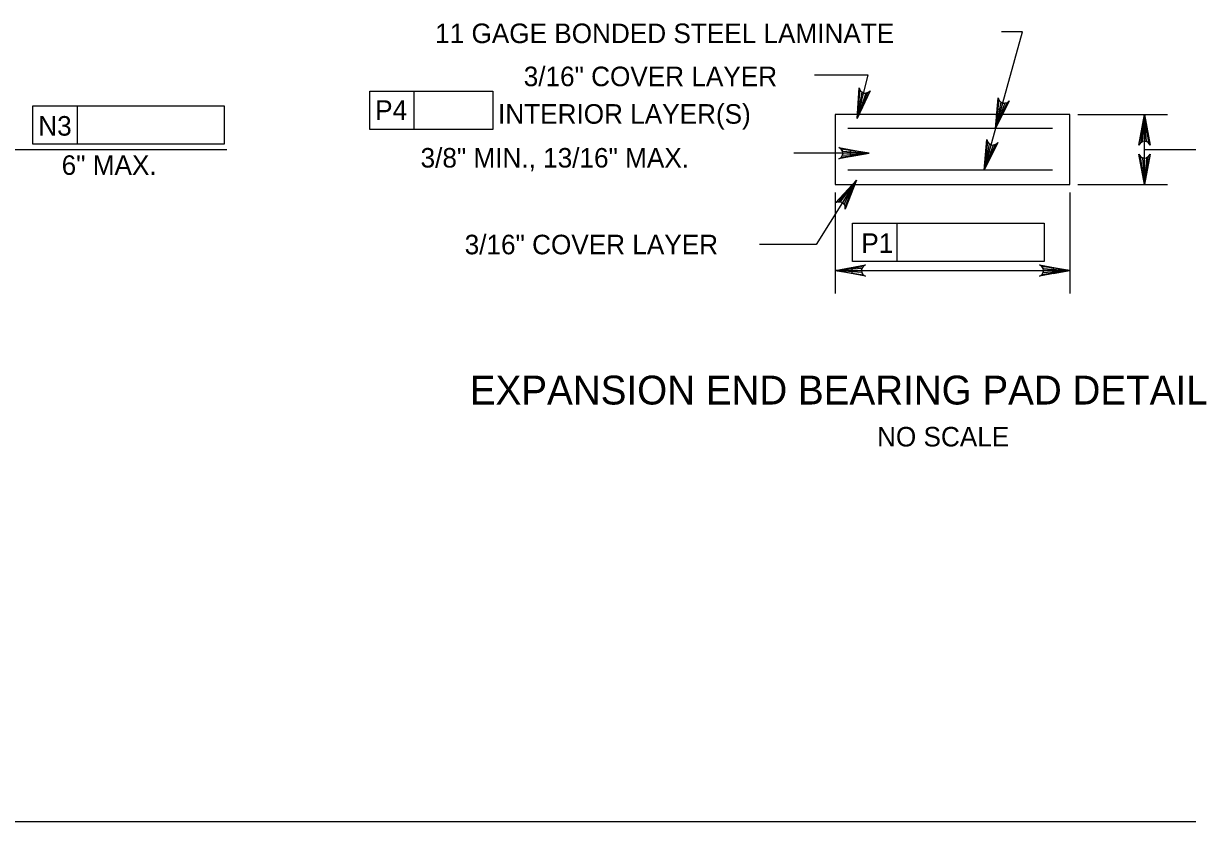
# Model space of a CAD drawing. Extents: x 638175 to 640495, y 294277 to 298435.
# Drawn here: x 639473 to 639651.7, y 297262.5 to 297385 of the extents above; entities that cross this region are included whole.
import ezdxf

# ---------------------------------------------------------------- set-up
doc = ezdxf.new("R2010")
doc.units = 0
for name, color, linetype in [('2', 7, 'Continuous'), ('3', 7, 'Continuous'), ('4', 7, 'Continuous'), ('5', 7, 'Continuous'), ('6', 7, 'Continuous'), ('7', 7, 'Continuous')]:
    doc.layers.add(name, color=color, linetype=linetype)

msp = doc.modelspace()

# ---------------------------------------------------------------- linework, layer by layer
at = {"layer": '2'}
for p, q in [((639597.54, 297359), (639597.54, 297343.49)), ((639633.57, 297359), (639633.57, 297343.49)), ((639597.54, 297347.03), (639633.57, 297347.03)), ((640102.46, 297262.46), (639316.46, 297262.46))]:
    msp.add_line(p, q, dxfattribs=at)
for points in [[(639600.91, 297370.35), (639601.22, 297375.08), (639601.38, 297374.67), (639601.63, 297374.41), (639601.92, 297374.28), (639602.24, 297374.26), (639602.59, 297374.36), (639602.92, 297374.64), (639600.91, 297370.35), (639602.59, 297374.36), (639602.24, 297374.26), (639600.91, 297370.35), (639601.92, 297374.28), (639601.63, 297374.41), (639600.91, 297370.35), (639601.38, 297374.67)], [(639622.18, 297368.81), (639622.58, 297373.54), (639622.73, 297373.13), (639622.98, 297372.86), (639623.27, 297372.73), (639623.58, 297372.7), (639623.93, 297372.79), (639624.27, 297373.07), (639622.18, 297368.81), (639623.93, 297372.79), (639623.58, 297372.7), (639622.18, 297368.81), (639623.27, 297372.73), (639622.98, 297372.86), (639622.18, 297368.81), (639622.73, 297373.13)], [(639645.03, 297370.96), (639645.9, 297366.3), (639645.65, 297366.66), (639645.34, 297366.84), (639645.03, 297366.9), (639644.71, 297366.84), (639644.4, 297366.66), (639644.15, 297366.3), (639645.03, 297370.96), (639644.4, 297366.66), (639644.71, 297366.84), (639645.03, 297370.96), (639645.03, 297366.9), (639645.34, 297366.84), (639645.03, 297370.96), (639645.65, 297366.66)], [(639602.79, 297365.04), (639598.13, 297364.17), (639598.49, 297364.41), (639598.68, 297364.73), (639598.73, 297365.04), (639598.68, 297365.35), (639598.49, 297365.66), (639598.13, 297365.91), (639602.79, 297365.04), (639598.49, 297365.66), (639598.68, 297365.35), (639602.79, 297365.04), (639598.73, 297365.04), (639598.68, 297364.73), (639602.79, 297365.04), (639598.49, 297364.41)], [(639620.41, 297362.42), (639620.81, 297367.14), (639620.96, 297366.73), (639621.21, 297366.47), (639621.49, 297366.33), (639621.81, 297366.3), (639622.16, 297366.4), (639622.5, 297366.68), (639620.41, 297362.42), (639622.16, 297366.4), (639621.81, 297366.3), (639620.41, 297362.42), (639621.49, 297366.33), (639621.21, 297366.47), (639620.41, 297362.42), (639620.96, 297366.73)], [(639645.03, 297360.23), (639644.15, 297364.89), (639644.4, 297364.53), (639644.71, 297364.34), (639645.03, 297364.29), (639645.34, 297364.34), (639645.65, 297364.53), (639645.9, 297364.89), (639645.03, 297360.23), (639645.65, 297364.53), (639645.34, 297364.34), (639645.03, 297360.23), (639645.03, 297364.29), (639644.71, 297364.34), (639645.03, 297360.23), (639644.4, 297364.53)], [(639600.82, 297360.89), (639599.09, 297356.48), (639599.07, 297356.92), (639598.91, 297357.24), (639598.67, 297357.45), (639598.38, 297357.57), (639598.01, 297357.58), (639597.61, 297357.41), (639600.82, 297360.89), (639598.01, 297357.58), (639598.38, 297357.57), (639600.82, 297360.89), (639598.67, 297357.45), (639598.91, 297357.24), (639600.82, 297360.89), (639599.07, 297356.92)], [(639597.54, 297347.03), (639602.2, 297347.9), (639601.84, 297347.65), (639601.66, 297347.34), (639601.6, 297347.03), (639601.66, 297346.72), (639601.84, 297346.4), (639602.2, 297346.16), (639597.54, 297347.03), (639601.84, 297346.4), (639601.66, 297346.72), (639597.54, 297347.03), (639601.6, 297347.03), (639601.66, 297347.34), (639597.54, 297347.03), (639601.84, 297347.65)], [(639633.57, 297347.03), (639628.91, 297346.16), (639629.27, 297346.4), (639629.45, 297346.72), (639629.51, 297347.03), (639629.45, 297347.34), (639629.27, 297347.65), (639628.91, 297347.9), (639633.57, 297347.03), (639629.27, 297347.65), (639629.45, 297347.34), (639633.57, 297347.03), (639629.51, 297347.03), (639629.45, 297346.72), (639633.57, 297347.03), (639629.27, 297346.4)]]:
    msp.add_lwpolyline(points, dxfattribs=at)
for points in [[(639600.1, 297347.46), (639600.1, 297346.6), (639597.54, 297347.03)], [(639631.01, 297347.46), (639631.01, 297346.6), (639633.57, 297347.03)]]:
    msp.add_lwpolyline(points, close=True, dxfattribs=at)
at = {"layer": '3'}
for p, q in [((639602.63, 297377.03), (639594.39, 297377.03)), ((639600.91, 297370.35), (639602.63, 297377.03)), ((639526.12, 297374.58), (639545.03, 297374.58)), ((639526.12, 297368.68), (639526.12, 297374.58)), ((639532.97, 297368.68), (639532.97, 297374.58)), ((639545.03, 297374.58), (639545.03, 297368.68)), ((639474.41, 297372.32), (639503.81, 297372.32)), ((639474.41, 297366.42), (639474.41, 297372.32)), ((639481.26, 297366.42), (639481.26, 297372.32)), ((639503.81, 297372.32), (639503.81, 297366.42)), ((639634.8, 297370.96), (639648.57, 297370.96)), ((639645.03, 297360.23), (639645.03, 297370.96)), ((639645.03, 297370.96), (639645.03, 297370.96)), ((639545.03, 297368.68), (639526.12, 297368.68)), ((639503.81, 297366.42), (639474.41, 297366.42)), ((639466.54, 297365.59), (639504.2, 297365.59)), ((639645.03, 297365.59), (639682.68, 297365.59)), ((639600.82, 297360.89), (639594.66, 297351.04)), ((639634.8, 297360.23), (639648.57, 297360.23)), ((639600.22, 297348.41), (639600.22, 297354.32)), ((639600.22, 297354.32), (639629.62, 297354.32)), ((639607.07, 297348.41), (639607.07, 297354.32)), ((639629.62, 297354.32), (639629.62, 297348.41)), ((639594.66, 297351.04), (639585.95, 297351.04)), ((639629.62, 297348.41), (639600.22, 297348.41))]:
    msp.add_line(p, q, dxfattribs=at)
for points in [[(639601.96, 297372.72), (639601.13, 297372.93), (639600.91, 297370.35)], [(639644.6, 297368.28), (639645.45, 297368.28), (639645.03, 297370.84)], [(639644.6, 297362.79), (639645.45, 297362.79), (639645.03, 297360.23)], [(639599.83, 297358.5), (639599.11, 297358.95), (639600.82, 297360.89)]]:
    msp.add_lwpolyline(points, close=True, dxfattribs=at)
at = {"layer": '4'}
for p, q in [((639633.57, 297370.96), (639597.54, 297370.96)), ((639597.54, 297370.96), (639597.54, 297360.23)), ((639633.57, 297360.23), (639633.57, 297370.96)), ((639630.9, 297368.81), (639599.52, 297368.81)), ((639630.9, 297362.42), (639599.52, 297362.42)), ((639597.54, 297360.23), (639633.57, 297360.23))]:
    msp.add_line(p, q, dxfattribs=at)
at = {"layer": '5'}
for p, q in [((639620.41, 297362.42), (639626.3, 297383.69)), ((639602.79, 297365.04), (639591.19, 297365.04))]:
    msp.add_line(p, q, dxfattribs=at)
for points in [[(639623.44, 297371.53), (639622.49, 297371.79), (639622.18, 297368.81)], [(639599.84, 297365.53), (639599.84, 297364.55), (639602.79, 297365.04)], [(639621.61, 297365.13), (639620.66, 297365.39), (639620.35, 297362.42)]]:
    msp.add_lwpolyline(points, close=True, dxfattribs=at)
at = {"layer": '6'}
msp.add_line((639626.3, 297383.69), (639623.09, 297383.69), dxfattribs=at)
at = {"layer": '7'}
for p, q in [((639633.57, 297370.96), (639633.57, 297370.96)), ((639597.54, 297360.23), (639597.54, 297360.23)), ((639633.57, 297360.23), (639633.57, 297360.23)), ((639597.54, 297347.03), (639597.54, 297347.03))]:
    msp.add_line(p, q, dxfattribs=at)

# ---------------------------------------------------------------- texts
at = {"layer": '3'}
for s, height, p in [('11 GAGE BONDED STEEL LAMINATE', 3, (639536.17, 297381.94)), ('3/16" COVER LAYER', 3, (639549.76, 297375.33)), ('P4', 3, (639526.96, 297370.16)), ('INTERIOR LAYER(S)', 3, (639545.82, 297369.57)), ('N3', 3, (639475.26, 297367.74)), ('3/8" MIN., 13/16" MAX.', 3, (639533.93, 297362.84)), ('6" MAX.', 3, (639478.85, 297361.72)), ('3/16" COVER LAYER', 3, (639540.7, 297349.53)), ('P1', 3, (639601.57, 297349.74)), ('EXPANSION END BEARING PAD DETAIL', 4.4292, (639541.49, 297326.48)), ('NO SCALE', 3, (639603.98, 297320.04))]:
    msp.add_text(s, height=height, dxfattribs=at).set_placement(p)

doc.saveas('drawing.dxf')
